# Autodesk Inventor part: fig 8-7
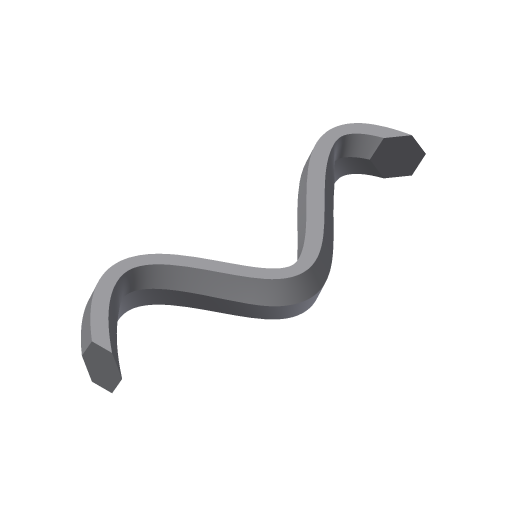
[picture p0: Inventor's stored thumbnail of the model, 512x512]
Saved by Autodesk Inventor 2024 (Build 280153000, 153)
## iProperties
Created: 2006-01
Part Number: fig 8-7
Document SubType Name: Modeling
Designer: CADCIM
Density: 1 g/cm^3
Material: Generic
Appearance: Default
Author: CADCIM
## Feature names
1. Sweep4
## Parameters: d3 = 0, d4 = 0
